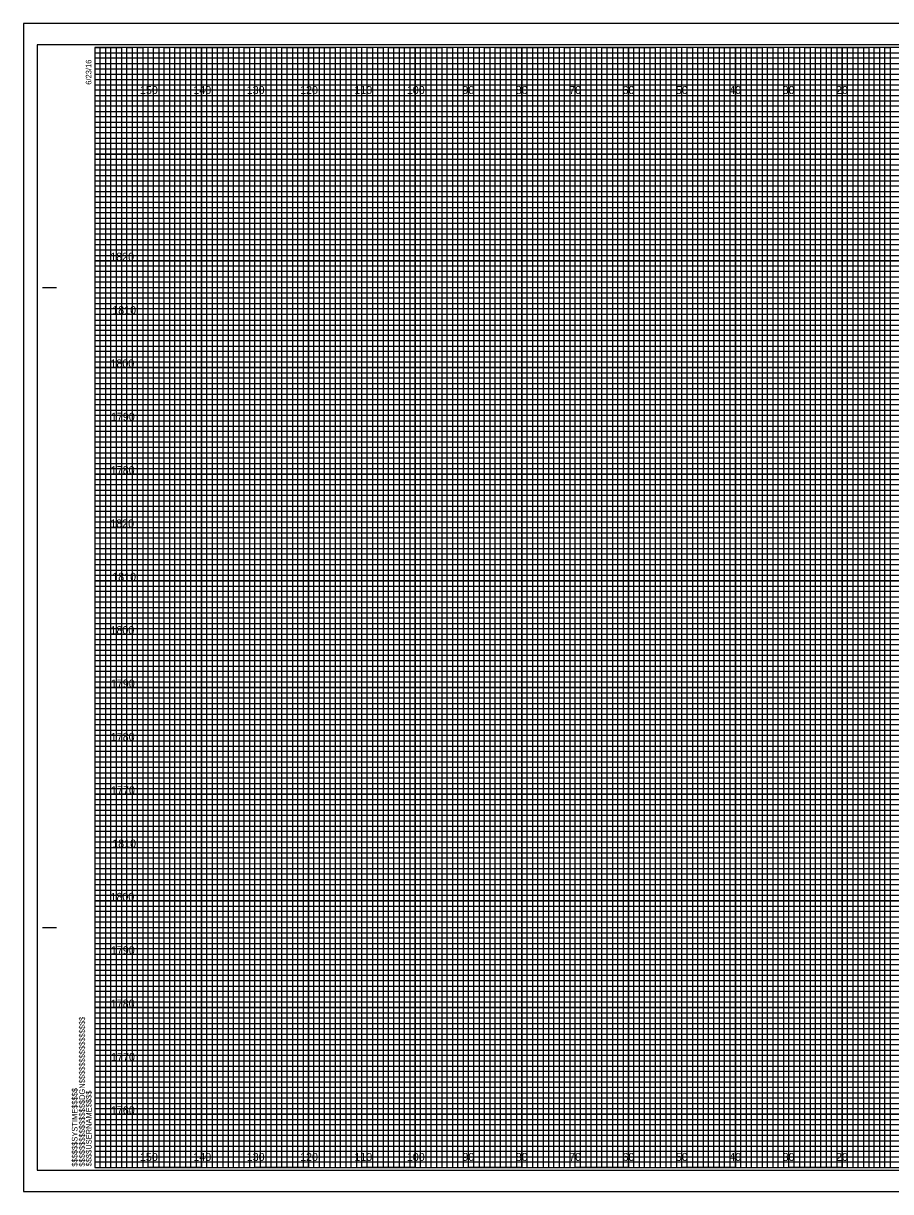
# Model space of a CAD drawing. Extents: x -163 to 174, y 11 to 1110.
# Drawn here: x -162.9 to -0.4, y 11.2 to 230.2 of the extents above; entities that cross this region are included whole.
import ezdxf

# ---------------------------------------------------------------- set-up
doc = ezdxf.new("R2010")
doc.units = 0
for name, color, linetype in [('Prop XS DDE', 7, 'Continuous'), ('Prop XS Earthwork Shape', 7, 'Continuous'), ('Prop XS Elevation Labels', 7, 'Continuous'), ('Sheet Cross Section CELL', 7, 'Continuous'), ('Sheet Cross Section Grid Middle CELL', 7, 'Continuous'), ('Sheet Cross Section Grid Minor 1 CELL', 7, 'Continuous'), ('Sheet Cross Section Grid Minor 2 CELL', 7, 'Continuous'), ('Sheet Cutting Line CELL', 7, 'Continuous'), ('Sheet DOT Grid CELL', 7, 'Continuous'), ('Sheet Plot Border Inside CELL', 7, 'Continuous'), ('Sheet Plot Border Outside CELL', 7, 'Continuous')]:
    doc.layers.add(name, color=color, linetype=linetype)

msp = doc.modelspace()

# ---------------------------------------------------------------- linework, layer by layer
at = {"layer": 'Prop XS DDE'}
for p, q in [((-139.53, 225.7), (-149.53, 225.7)), ((-139.53, 15.7), (-139.53, 225.7)), ((-119.53, 225.7), (-129.53, 225.7)), ((-129.53, 225.7), (-129.53, 15.7)), ((-119.53, 15.7), (-119.53, 225.7)), ((-99.53, 225.7), (-109.53, 225.7)), ((-109.53, 225.7), (-109.53, 15.7)), ((-99.53, 15.7), (-99.53, 225.7)), ((-79.53, 225.7), (-89.53, 225.7)), ((-89.53, 225.7), (-89.53, 15.7)), ((-79.53, 15.7), (-79.53, 225.7)), ((-59.53, 225.7), (-69.53, 225.7)), ((-69.53, 225.7), (-69.53, 15.7)), ((-59.53, 15.7), (-59.53, 225.7)), ((-39.53, 225.7), (-49.53, 225.7)), ((-49.53, 225.7), (-49.53, 15.7)), ((-39.53, 15.7), (-39.53, 225.7)), ((-19.53, 225.7), (-29.53, 225.7)), ((-29.53, 225.7), (-29.53, 15.7)), ((-19.53, 15.7), (-19.53, 225.7)), ((0.47, 225.7), (-9.53, 225.7)), ((-9.53, 225.7), (-9.53, 15.7)), ((-129.53, 15.7), (-139.53, 15.7)), ((-109.53, 15.7), (-119.53, 15.7)), ((-89.53, 15.7), (-99.53, 15.7)), ((-69.53, 15.7), (-79.53, 15.7)), ((-49.53, 15.7), (-59.53, 15.7)), ((-29.53, 15.7), (-39.53, 15.7)), ((-9.53, 15.7), (-19.53, 15.7))]:
    msp.add_line(p, q, dxfattribs=at)
for points in [[(-149.53, 215.7), (170.47, 215.7), (170.47, 205.7), (-149.53, 205.7)], [(-149.53, 195.7), (170.47, 195.7), (170.47, 185.7), (-149.53, 185.7)], [(-149.53, 175.7), (170.47, 175.7), (170.47, 165.7), (-149.53, 165.7)], [(-149.53, 155.7), (170.47, 155.7), (170.47, 145.7), (-149.53, 145.7)], [(-149.53, 135.7), (170.47, 135.7), (170.47, 125.7), (-149.53, 125.7)], [(-149.53, 115.7), (170.47, 115.7), (170.47, 105.7), (-149.53, 105.7)], [(-149.53, 95.7), (170.47, 95.7), (170.47, 85.7), (-149.53, 85.7)], [(-149.53, 75.7), (170.47, 75.7), (170.47, 65.7), (-149.53, 65.7)], [(-149.53, 55.7), (170.47, 55.7), (170.47, 45.7), (-149.53, 45.7)], [(-149.53, 35.7), (170.47, 35.7), (170.47, 25.7), (-149.53, 25.7)]]:
    msp.add_lwpolyline(points, dxfattribs=at)
at = {"layer": 'Sheet Cross Section CELL'}
for p, q in [((-159.33, 180.7), (-156.83, 180.7)), ((-159.23, 180.7), (-156.73, 180.7)), ((-159.33, 60.7), (-156.83, 60.7)), ((-159.23, 60.7), (-156.73, 60.7)), ((-149.53, 15.7), (-149.53, 15.7)), ((-149.53, 15.7), (-149.53, 15.7)), ((-149.53, 15.7), (-149.53, 15.7)), ((-149.53, 15.7), (-149.53, 15.7)), ((-149.53, 15.7), (-149.53, 15.7)), ((-149.53, 15.7), (-149.53, 15.7)), ((-149.53, 15.7), (-149.53, 15.7))]:
    msp.add_line(p, q, dxfattribs=at)
msp.add_lwpolyline([(170.47, 225.7), (-149.53, 225.7), (-149.53, 15.7), (170.47, 15.7)], close=True, dxfattribs=at)
at = {"layer": 'Sheet Cross Section Grid Middle CELL'}
for points in [[(-149.53, 225.7), (-144.53, 225.7), (-144.53, 15.7), (-134.53, 15.7), (-134.53, 225.7), (-124.53, 225.7), (-124.53, 15.7), (-114.53, 15.7), (-114.53, 225.7), (-104.53, 225.7), (-104.53, 15.7), (-94.53, 15.7), (-94.53, 225.7), (-84.53, 225.7), (-84.53, 15.7), (-74.53, 15.7), (-74.53, 225.7), (-64.53, 225.7), (-64.53, 15.7), (-54.53, 15.7), (-54.53, 225.7), (-44.53, 225.7), (-44.53, 15.7), (-34.53, 15.7), (-34.53, 225.7), (-24.53, 225.7), (-24.53, 15.7), (-14.53, 15.7), (-14.53, 225.7), (-4.53, 225.7), (-4.53, 15.7), (5.47, 15.7)], [(-149.53, 220.7), (125.47, 220.7)], [(-149.53, 200.7), (170.47, 200.7), (170.47, 210.7), (-149.53, 210.7)], [(-149.53, 180.7), (170.47, 180.7), (170.47, 190.7), (-149.53, 190.7)], [(-149.53, 160.7), (170.47, 160.7), (170.47, 170.7), (-149.53, 170.7)], [(-149.53, 140.7), (170.47, 140.7), (170.47, 150.7), (-149.53, 150.7)], [(-149.53, 120.7), (170.47, 120.7), (170.47, 130.7), (-149.53, 130.7)], [(-149.53, 100.7), (170.47, 100.7), (170.47, 110.7), (-149.53, 110.7)], [(-149.53, 80.7), (170.47, 80.7), (170.47, 90.7), (-149.53, 90.7)], [(-149.53, 60.7), (170.47, 60.7), (170.47, 70.7), (-149.53, 70.7)], [(-149.53, 40.7), (170.47, 40.7), (170.47, 50.7), (-149.53, 50.7)], [(-149.53, 20.7), (170.47, 20.7), (170.47, 30.7), (-149.53, 30.7)]]:
    msp.add_lwpolyline(points, dxfattribs=at)
at = {"layer": 'Sheet Cross Section Grid Minor 1 CELL'}
for p, q in [((-149.53, 224.7), (110.47, 224.7)), ((110.47, 223.68), (-149.53, 223.68)), ((-149.53, 223.68), (-149.53, 222.7)), ((-149.53, 222.7), (110.47, 222.7)), ((110.47, 221.59), (-149.53, 221.59)), ((-149.53, 221.59), (-149.53, 219.7)), ((-149.53, 219.7), (170.47, 219.7))]:
    msp.add_line(p, q, dxfattribs=at)
for points in [[(-149.53, 218.7), (120.47, 218.7), (170.47, 218.7), (170.47, 217.7), (-149.53, 217.7)], [(-149.53, 216.7), (170.47, 216.7), (170.47, 214.7), (-149.53, 214.7)], [(-149.53, 213.7), (170.47, 213.7), (170.47, 212.7), (-149.53, 212.68)], [(-149.53, 211.7), (170.47, 211.7), (170.47, 209.7), (-149.53, 209.7)], [(-149.53, 208.7), (170.47, 208.7), (170.47, 207.7), (-149.53, 207.7)], [(-149.53, 206.7), (170.47, 206.7), (170.47, 204.7), (-149.53, 204.7)], [(-149.53, 203.7), (170.47, 203.7), (170.47, 202.7), (-149.53, 202.7)], [(-149.53, 201.7), (170.47, 201.7), (170.47, 199.7), (-149.53, 199.7)], [(-149.53, 198.7), (170.47, 198.7), (170.47, 197.7), (-149.53, 197.7)], [(-149.53, 196.7), (170.47, 196.7), (170.47, 194.7), (-149.53, 194.7)], [(-149.53, 193.7), (170.47, 193.7), (170.47, 192.7), (-149.53, 192.7)], [(-149.53, 191.7), (170.47, 191.7), (170.47, 189.65), (170.47, 188.7), (170.47, 187.7), (-149.53, 187.7)], [(-149.53, 189.7), (170.47, 189.7), (170.47, 188.7), (-149.53, 188.7)], [(-149.53, 186.7), (170.47, 186.7), (170.47, 184.7), (-149.53, 184.73)], [(-149.53, 184.73), (170.47, 184.7), (170.47, 183.7), (-149.53, 183.7)], [(-149.53, 182.7), (170.47, 182.7), (170.47, 181.7), (-149.53, 181.7)], [(-149.53, 179.7), (170.47, 179.7), (170.47, 178.7), (-149.53, 178.7)], [(-149.53, 177.7), (170.47, 177.7), (170.47, 176.7), (-149.53, 176.7)], [(-149.6, 174.59), (170.47, 174.59), (170.47, 173.58), (-149.6, 173.58)], [(-149.53, 172.7), (170.47, 172.7), (170.47, 171.7), (-149.53, 171.7)], [(-149.53, 169.7), (170.47, 169.7), (170.47, 168.7), (-149.53, 168.7)], [(-149.53, 167.7), (170.47, 167.7), (170.47, 166.7), (-149.53, 166.7)], [(-149.53, 164.7), (170.47, 164.7), (170.47, 163.7), (-149.53, 163.7)], [(-149.53, 162.7), (170.47, 162.7), (170.47, 161.7), (-149.53, 161.7)], [(-149.53, 159.7), (170.47, 159.7), (170.47, 158.7), (-149.53, 158.7)], [(-149.53, 157.7), (170.47, 157.7), (170.47, 156.7), (-149.53, 156.7)], [(-149.53, 154.7), (170.47, 154.7), (170.46, 153.68), (-149.53, 153.7)], [(-149.53, 152.7), (170.47, 152.7), (170.47, 151.7), (-149.53, 151.7)], [(-149.53, 149.7), (170.47, 149.7), (170.47, 148.7), (-149.53, 148.7)], [(-149.53, 147.7), (170.47, 147.7), (170.47, 146.7), (-149.53, 146.7)], [(-149.53, 144.7), (170.47, 144.7), (170.47, 143.7), (-149.53, 143.7)], [(-149.53, 142.7), (170.47, 142.7), (170.47, 141.7), (-149.53, 141.7)], [(-149.53, 139.7), (170.47, 139.7), (170.47, 138.7), (-149.53, 138.7)], [(-149.53, 137.7), (170.47, 137.7), (170.47, 136.7), (-149.53, 136.7)], [(-149.53, 134.7), (170.47, 134.7), (170.47, 133.7), (-149.53, 133.7)], [(-149.53, 132.69), (170.54, 132.61), (170.47, 131.7), (-149.53, 131.7)], [(-149.53, 129.7), (170.47, 129.7), (170.47, 128.7), (-149.53, 128.7)], [(-149.53, 127.7), (170.47, 127.7), (170.47, 126.7), (-149.53, 126.7)], [(-149.53, 124.7), (170.47, 124.7), (170.47, 123.7), (-149.53, 123.7)], [(-149.53, 122.7), (170.47, 122.7), (170.47, 121.7), (-149.53, 121.7)], [(-149.53, 119.7), (170.47, 119.7), (170.47, 118.7), (-149.53, 118.7)], [(-149.53, 117.7), (170.47, 117.7), (170.47, 116.7), (-149.53, 116.7)], [(-149.53, 114.7), (170.47, 114.7), (170.47, 113.7), (-149.53, 113.7)], [(-149.53, 112.7), (170.47, 112.7), (170.47, 111.7), (-149.53, 111.7)], [(-149.53, 109.7), (170.47, 109.7), (170.47, 108.7), (-149.53, 108.7)], [(-149.53, 107.7), (170.47, 107.7), (170.47, 106.7), (-149.53, 106.7)], [(-149.53, 104.7), (170.47, 104.7), (170.47, 103.7), (-149.53, 103.7)], [(-149.53, 102.7), (170.47, 102.7), (170.47, 101.7), (-149.53, 101.7)], [(-149.53, 99.7), (170.47, 99.7), (170.47, 98.7), (-149.53, 98.7)], [(-149.53, 97.7), (170.47, 97.7), (170.47, 96.7), (-149.53, 96.7)], [(-149.53, 94.7), (170.47, 94.7), (170.46, 93.68), (-149.53, 93.7)], [(-149.53, 92.7), (170.47, 92.7), (170.47, 91.7), (-149.53, 91.7)], [(-149.53, 89.7), (170.47, 89.7), (170.47, 88.7), (-149.53, 88.7)], [(-149.53, 87.7), (170.47, 87.7), (170.47, 86.7), (-149.53, 86.7)], [(-149.53, 84.7), (170.47, 84.7), (170.47, 83.7), (-149.53, 83.7)], [(-149.53, 82.7), (170.47, 82.7), (170.47, 81.7), (-149.53, 81.7)], [(-149.53, 79.7), (170.47, 79.7), (170.47, 78.7), (-149.53, 78.7)], [(-149.53, 77.7), (170.47, 77.7), (170.47, 76.7), (-149.53, 76.7)], [(-149.53, 74.7), (170.47, 74.7), (170.47, 73.7), (-149.53, 73.7)], [(-149.53, 72.69), (170.54, 72.61), (170.47, 71.7), (-149.53, 71.7)], [(-149.53, 69.7), (170.47, 69.7), (170.47, 68.7), (-149.53, 68.7)], [(-149.53, 67.7), (170.47, 67.7), (170.47, 66.7), (-149.53, 66.7)], [(-149.53, 64.7), (170.47, 64.7), (170.47, 63.7), (-149.53, 63.7)], [(-149.53, 62.7), (170.47, 62.7), (170.47, 61.7), (-149.53, 61.7)], [(-149.53, 59.7), (170.47, 59.7), (170.47, 58.7), (-149.53, 58.7)], [(-149.53, 57.7), (170.47, 57.7), (170.47, 56.7), (-149.53, 56.7)], [(-149.53, 54.7), (170.47, 54.7), (170.47, 53.7), (-149.53, 53.7)], [(-149.53, 52.7), (170.47, 52.7), (170.47, 51.7), (-149.53, 51.7)], [(-149.53, 49.7), (170.47, 49.7), (170.47, 48.7), (-149.53, 48.7)], [(-149.53, 47.7), (170.47, 47.7), (170.47, 46.7), (-149.53, 46.7)], [(-149.53, 44.7), (170.47, 44.7), (170.47, 43.7), (-149.53, 43.7)], [(-149.53, 42.7), (170.47, 42.7), (170.47, 41.7), (-149.53, 41.7)], [(-149.53, 39.7), (170.47, 39.7), (170.47, 38.7), (-149.53, 38.7)], [(-149.53, 37.7), (170.47, 37.7), (170.47, 36.7), (-149.53, 36.7)], [(-149.53, 34.7), (170.47, 34.7), (170.47, 33.7), (-149.53, 33.7)], [(-149.53, 32.7), (170.47, 32.7), (170.47, 31.7), (-149.53, 31.7)], [(-149.53, 29.7), (170.47, 29.7), (170.47, 28.7), (-149.53, 28.7)], [(-149.53, 27.7), (170.47, 27.7), (170.47, 26.7), (-149.53, 26.7)], [(-149.53, 24.7), (170.47, 24.7), (170.47, 23.7), (-149.53, 23.7)], [(-149.53, 22.7), (170.47, 22.7), (170.47, 21.7), (-149.53, 21.7)], [(-149.53, 19.7), (170.47, 19.7), (170.47, 18.7), (-149.53, 18.7)], [(-149.53, 17.7), (170.47, 17.7), (170.47, 16.7), (-149.53, 16.7)]]:
    msp.add_lwpolyline(points, dxfattribs=at)
at = {"layer": 'Sheet Cross Section Grid Minor 2 CELL'}
for points in [[(-149.53, 15.7), (-148.53, 15.7), (-148.53, 225.7), (-147.53, 225.7), (-147.53, 15.7)], [(-147.53, 15.7), (-146.53, 15.7), (-146.53, 225.7), (-145.53, 225.7), (-145.53, 15.7)], [(-144.53, 15.7), (-143.53, 15.7), (-143.53, 225.7), (-142.53, 225.7), (-142.53, 15.7)], [(-142.53, 15.7), (-141.53, 15.7), (-141.53, 225.7), (-140.53, 225.7), (-140.53, 15.7)], [(-139.53, 15.7), (-138.53, 15.7), (-138.53, 225.7), (-137.53, 225.7), (-137.53, 15.7)], [(-137.53, 15.7), (-136.53, 15.7), (-136.53, 225.7), (-135.53, 225.7), (-135.53, 15.7)], [(-134.53, 15.7), (-133.53, 15.7), (-133.53, 225.7), (-132.53, 225.7), (-132.53, 15.7)], [(-132.53, 15.7), (-131.53, 15.7), (-131.53, 225.7), (-130.53, 225.7), (-130.53, 15.7)], [(-129.53, 15.7), (-128.53, 15.7), (-128.53, 225.7), (-127.53, 225.7), (-127.53, 15.7)], [(-127.53, 15.7), (-126.53, 15.7), (-126.53, 225.7), (-125.53, 225.7), (-125.53, 15.7)], [(-124.53, 15.7), (-123.53, 15.7), (-123.53, 225.7), (-122.53, 225.7), (-122.53, 15.7)], [(-122.53, 15.7), (-121.53, 15.7), (-121.53, 225.7), (-120.53, 225.7), (-120.53, 15.7)], [(-119.53, 15.7), (-118.53, 15.7), (-118.53, 225.7), (-117.53, 225.7), (-117.53, 15.7)], [(-117.53, 15.7), (-116.53, 15.7), (-116.53, 225.7), (-115.53, 225.7), (-115.53, 15.7)], [(-114.53, 15.7), (-113.53, 15.7), (-113.53, 225.7), (-112.53, 225.7), (-112.53, 15.7)], [(-112.53, 15.7), (-111.53, 15.7), (-111.53, 225.7), (-110.53, 225.7), (-110.53, 15.7)], [(-109.53, 15.7), (-108.53, 15.7), (-108.53, 225.7), (-107.53, 225.7), (-107.53, 15.7)], [(-107.53, 15.7), (-106.53, 15.7), (-106.53, 225.7), (-105.53, 225.7), (-105.53, 15.7)], [(-104.53, 15.7), (-103.53, 15.7), (-103.53, 225.7), (-102.53, 225.7), (-102.53, 15.7)], [(-102.53, 15.7), (-101.53, 15.7), (-101.53, 225.7), (-100.53, 225.7), (-100.53, 15.7)], [(-99.53, 15.7), (-98.53, 15.7), (-98.53, 225.7), (-97.53, 225.7), (-97.53, 15.7)], [(-97.53, 15.7), (-96.53, 15.7), (-96.53, 225.7), (-95.53, 225.7), (-95.53, 15.7)], [(-94.53, 15.7), (-93.53, 15.7), (-93.53, 225.7), (-92.53, 225.7), (-92.53, 15.7)], [(-92.53, 15.7), (-91.53, 15.7), (-91.53, 225.7), (-90.53, 225.7), (-90.53, 15.7)], [(-89.53, 15.7), (-88.53, 15.7), (-88.53, 225.7), (-87.53, 225.7), (-87.53, 15.7)], [(-87.53, 15.7), (-86.53, 15.7), (-86.53, 225.7), (-85.53, 225.7), (-85.53, 15.7)], [(-84.53, 15.7), (-83.53, 15.7), (-83.53, 225.7), (-82.53, 225.7), (-82.53, 15.7)], [(-82.53, 15.7), (-81.53, 15.7), (-81.53, 225.7), (-80.53, 225.7), (-80.53, 15.7)], [(-79.53, 15.7), (-78.53, 15.7), (-78.53, 225.7), (-77.53, 225.7), (-77.53, 15.7)], [(-77.53, 15.7), (-76.53, 15.7), (-76.53, 225.7), (-75.53, 225.7), (-75.53, 15.7)], [(-74.53, 15.7), (-73.53, 15.7), (-73.53, 225.7), (-72.53, 225.7), (-72.53, 15.7)], [(-72.53, 15.7), (-71.53, 15.7), (-71.53, 225.7), (-70.53, 225.7), (-70.53, 15.7)], [(-69.53, 15.7), (-68.53, 15.7), (-68.53, 225.7), (-67.53, 225.7), (-67.53, 15.7)], [(-67.53, 15.7), (-66.53, 15.7), (-66.53, 225.7), (-65.53, 225.7), (-65.53, 15.7)], [(-64.53, 15.7), (-63.53, 15.7), (-63.53, 225.7), (-62.53, 225.7), (-62.53, 15.7)], [(-62.53, 15.7), (-61.53, 15.7), (-61.53, 225.7), (-60.53, 225.7), (-60.53, 15.7)], [(-59.53, 15.7), (-58.53, 15.7), (-58.53, 225.7), (-57.53, 225.7), (-57.53, 15.7)], [(-57.53, 15.7), (-56.53, 15.7), (-56.53, 225.7), (-55.53, 225.7), (-55.53, 15.7)], [(-54.53, 15.7), (-53.53, 15.7), (-53.53, 225.7), (-52.53, 225.7), (-52.53, 15.7)], [(-52.53, 15.7), (-51.53, 15.7), (-51.53, 225.7), (-50.53, 225.7), (-50.53, 15.7)], [(-49.53, 15.7), (-48.53, 15.7), (-48.53, 225.7), (-47.53, 225.7), (-47.53, 15.7)], [(-47.53, 15.7), (-46.53, 15.7), (-46.53, 225.7), (-45.53, 225.7), (-45.53, 15.7)], [(-44.53, 15.7), (-43.53, 15.7), (-43.53, 225.7), (-42.53, 225.7), (-42.53, 15.7)], [(-42.53, 15.7), (-41.53, 15.7), (-41.53, 225.7), (-40.53, 225.7), (-40.53, 15.7)], [(-39.53, 15.7), (-38.53, 15.7), (-38.53, 225.7), (-37.53, 225.7), (-37.53, 15.7)], [(-37.53, 15.7), (-36.53, 15.7), (-36.53, 225.7), (-35.53, 225.7), (-35.53, 15.7)], [(-34.53, 15.7), (-33.53, 15.7), (-33.53, 225.7), (-32.53, 225.7), (-32.53, 15.7)], [(-32.53, 15.7), (-31.53, 15.7), (-31.53, 225.7), (-30.53, 225.7), (-30.53, 15.7)], [(-29.53, 15.7), (-28.53, 15.7), (-28.53, 225.7), (-27.53, 225.7), (-27.53, 15.7)], [(-27.53, 15.7), (-26.53, 15.7), (-26.53, 225.7), (-25.53, 225.7), (-25.53, 15.7)], [(-24.53, 15.7), (-23.53, 15.7), (-23.53, 225.7), (-22.53, 225.7), (-22.53, 15.7)], [(-22.53, 15.7), (-21.53, 15.7), (-21.53, 225.7), (-20.53, 225.7), (-20.53, 15.7)], [(-19.53, 15.7), (-18.53, 15.7), (-18.53, 225.7), (-17.53, 225.7), (-17.53, 15.7)], [(-17.53, 15.7), (-16.53, 15.7), (-16.53, 225.7), (-15.53, 225.7), (-15.53, 15.7)], [(-14.53, 15.7), (-13.53, 15.7), (-13.53, 225.7), (-12.53, 225.7), (-12.53, 15.7)], [(-12.53, 15.7), (-11.53, 15.7), (-11.53, 225.7), (-10.53, 225.7), (-10.53, 15.7)], [(-9.53, 15.7), (-8.53, 15.7), (-8.53, 225.7), (-7.53, 225.7), (-7.53, 15.7)], [(-7.53, 15.7), (-6.53, 15.7), (-6.53, 225.7), (-5.53, 225.7), (-5.53, 15.7)], [(-4.53, 15.7), (-3.53, 15.7), (-3.53, 225.7), (-2.53, 225.7), (-2.53, 15.7)], [(-2.53, 15.7), (-1.53, 15.7), (-1.53, 225.7), (-0.53, 225.7), (-0.53, 15.7)]]:
    msp.add_lwpolyline(points, dxfattribs=at)
at = {"layer": 'Sheet Cutting Line CELL'}
for p, q in [((173.77, 230.2), (-162.93, 230.2)), ((-162.93, 230.2), (-162.93, 11.2)), ((-162.93, 11.2), (173.77, 11.2))]:
    msp.add_line(p, q, dxfattribs=at)
at = {"layer": 'Sheet DOT Grid CELL'}
for p, q in [((-139.53, 15.7), (-139.53, 225.7)), ((-129.53, 15.7), (-129.53, 225.7)), ((-119.53, 15.7), (-119.53, 225.7)), ((-109.53, 15.7), (-109.53, 225.7)), ((-99.53, 15.7), (-99.53, 225.7)), ((-89.53, 15.7), (-89.53, 225.7)), ((-79.53, 15.7), (-79.53, 225.7)), ((-69.53, 15.7), (-69.53, 225.7)), ((-59.53, 15.7), (-59.53, 225.7)), ((-49.53, 15.7), (-49.53, 225.7)), ((-39.53, 15.7), (-39.53, 225.7)), ((-29.53, 15.7), (-29.53, 225.7)), ((-19.53, 15.7), (-19.53, 225.7)), ((-9.53, 15.7), (-9.53, 225.7)), ((-149.53, 215.7), (170.47, 215.7)), ((-149.53, 205.7), (170.47, 205.7)), ((-149.53, 195.7), (170.47, 195.7)), ((-149.53, 185.7), (170.47, 185.7)), ((-149.53, 175.7), (170.47, 175.7)), ((-149.53, 165.7), (170.47, 165.7)), ((-149.53, 155.7), (170.47, 155.7)), ((-149.53, 145.7), (170.47, 145.7)), ((-149.53, 135.7), (170.47, 135.7)), ((-149.53, 125.7), (170.47, 125.7)), ((-149.53, 115.7), (170.47, 115.7)), ((-149.53, 105.7), (170.47, 105.7)), ((-149.53, 95.7), (170.47, 95.7)), ((-149.53, 85.7), (170.47, 85.7)), ((-149.53, 75.7), (170.47, 75.7)), ((-149.53, 65.7), (170.47, 65.7)), ((-149.53, 55.7), (170.47, 55.7)), ((-149.53, 45.7), (170.47, 45.7)), ((-149.53, 35.7), (170.47, 35.7)), ((-149.53, 25.7), (170.47, 25.7))]:
    msp.add_line(p, q, dxfattribs=at)
at = {"layer": 'Sheet Plot Border Inside CELL'}
msp.add_lwpolyline([(-160.33, 15.2), (172.87, 15.2), (172.87, 226.2), (-160.33, 226.2)], close=True, dxfattribs=at)
at = {"layer": 'Sheet Plot Border Outside CELL'}
msp.add_lwpolyline([(-162.93, 11.2), (173.77, 11.2), (173.77, 230.2), (-162.93, 230.2)], close=True, dxfattribs=at)

# ---------------------------------------------------------------- texts
at = {"layer": 'Prop XS Earthwork Shape'}
for s, p in [('150', (-141.08, 216.95)), ('140', (-131.08, 216.95)), ('130', (-121.08, 216.95)), ('120', (-111.08, 216.95)), ('110', (-100.91, 216.95)), ('100', (-91.08, 216.95)), ('90', (-80.67, 216.95)), ('80', (-70.67, 216.95)), ('70', (-60.67, 216.95)), ('60', (-50.67, 216.95)), ('50', (-40.67, 216.95)), ('40', (-30.67, 216.95)), ('30', (-20.67, 216.95)), ('20', (-10.67, 216.95)), ('150', (-141.08, 16.95)), ('140', (-131.08, 16.95)), ('130', (-121.08, 16.95)), ('120', (-111.08, 16.95)), ('110', (-100.91, 16.95)), ('100', (-91.08, 16.95)), ('90', (-80.67, 16.95)), ('80', (-70.67, 16.95)), ('70', (-60.67, 16.95)), ('60', (-50.67, 16.95)), ('50', (-40.67, 16.95)), ('40', (-30.67, 16.95)), ('30', (-20.67, 16.95)), ('20', (-10.67, 16.95))]:
    msp.add_text(s, height=1.5, dxfattribs=at).set_placement(p)
at = {"layer": 'Prop XS Elevation Labels'}
for s, p in [('1820', (-146.65, 185.7)), ('1810', (-146.28, 175.7)), ('1800', (-146.61, 165.7)), ('1790', (-146.53, 155.7)), ('1780', (-146.55, 145.7)), ('1820', (-146.65, 135.7)), ('1810', (-146.28, 125.7)), ('1800', (-146.61, 115.7)), ('1790', (-146.53, 105.7)), ('1780', (-146.55, 95.7)), ('1770', (-146.49, 85.7)), ('1810', (-146.28, 75.7)), ('1800', (-146.61, 65.7)), ('1790', (-146.53, 55.7)), ('1780', (-146.55, 45.7)), ('1770', (-146.49, 35.7)), ('1760', (-146.53, 25.7))]:
    msp.add_text(s, height=1.5, dxfattribs=at).set_placement(p)
at = {"layer": 'Sheet Cross Section CELL'}
for s, p in [('6/23/16', (-150.18, 218.7)), ('$$$$$$$$$$$$$$$$DGN$$$$$$$$$$$$$$$$', (-151.41, 15.88)), ('$$$$$$SYSTIME$$$$$', (-152.79, 15.88)), ('$$$$USERNAME$$$$', (-150.15, 15.93))]:
    msp.add_text(s, height=1.05, rotation=90, dxfattribs=at).set_placement(p)

doc.saveas('drawing.dxf')
